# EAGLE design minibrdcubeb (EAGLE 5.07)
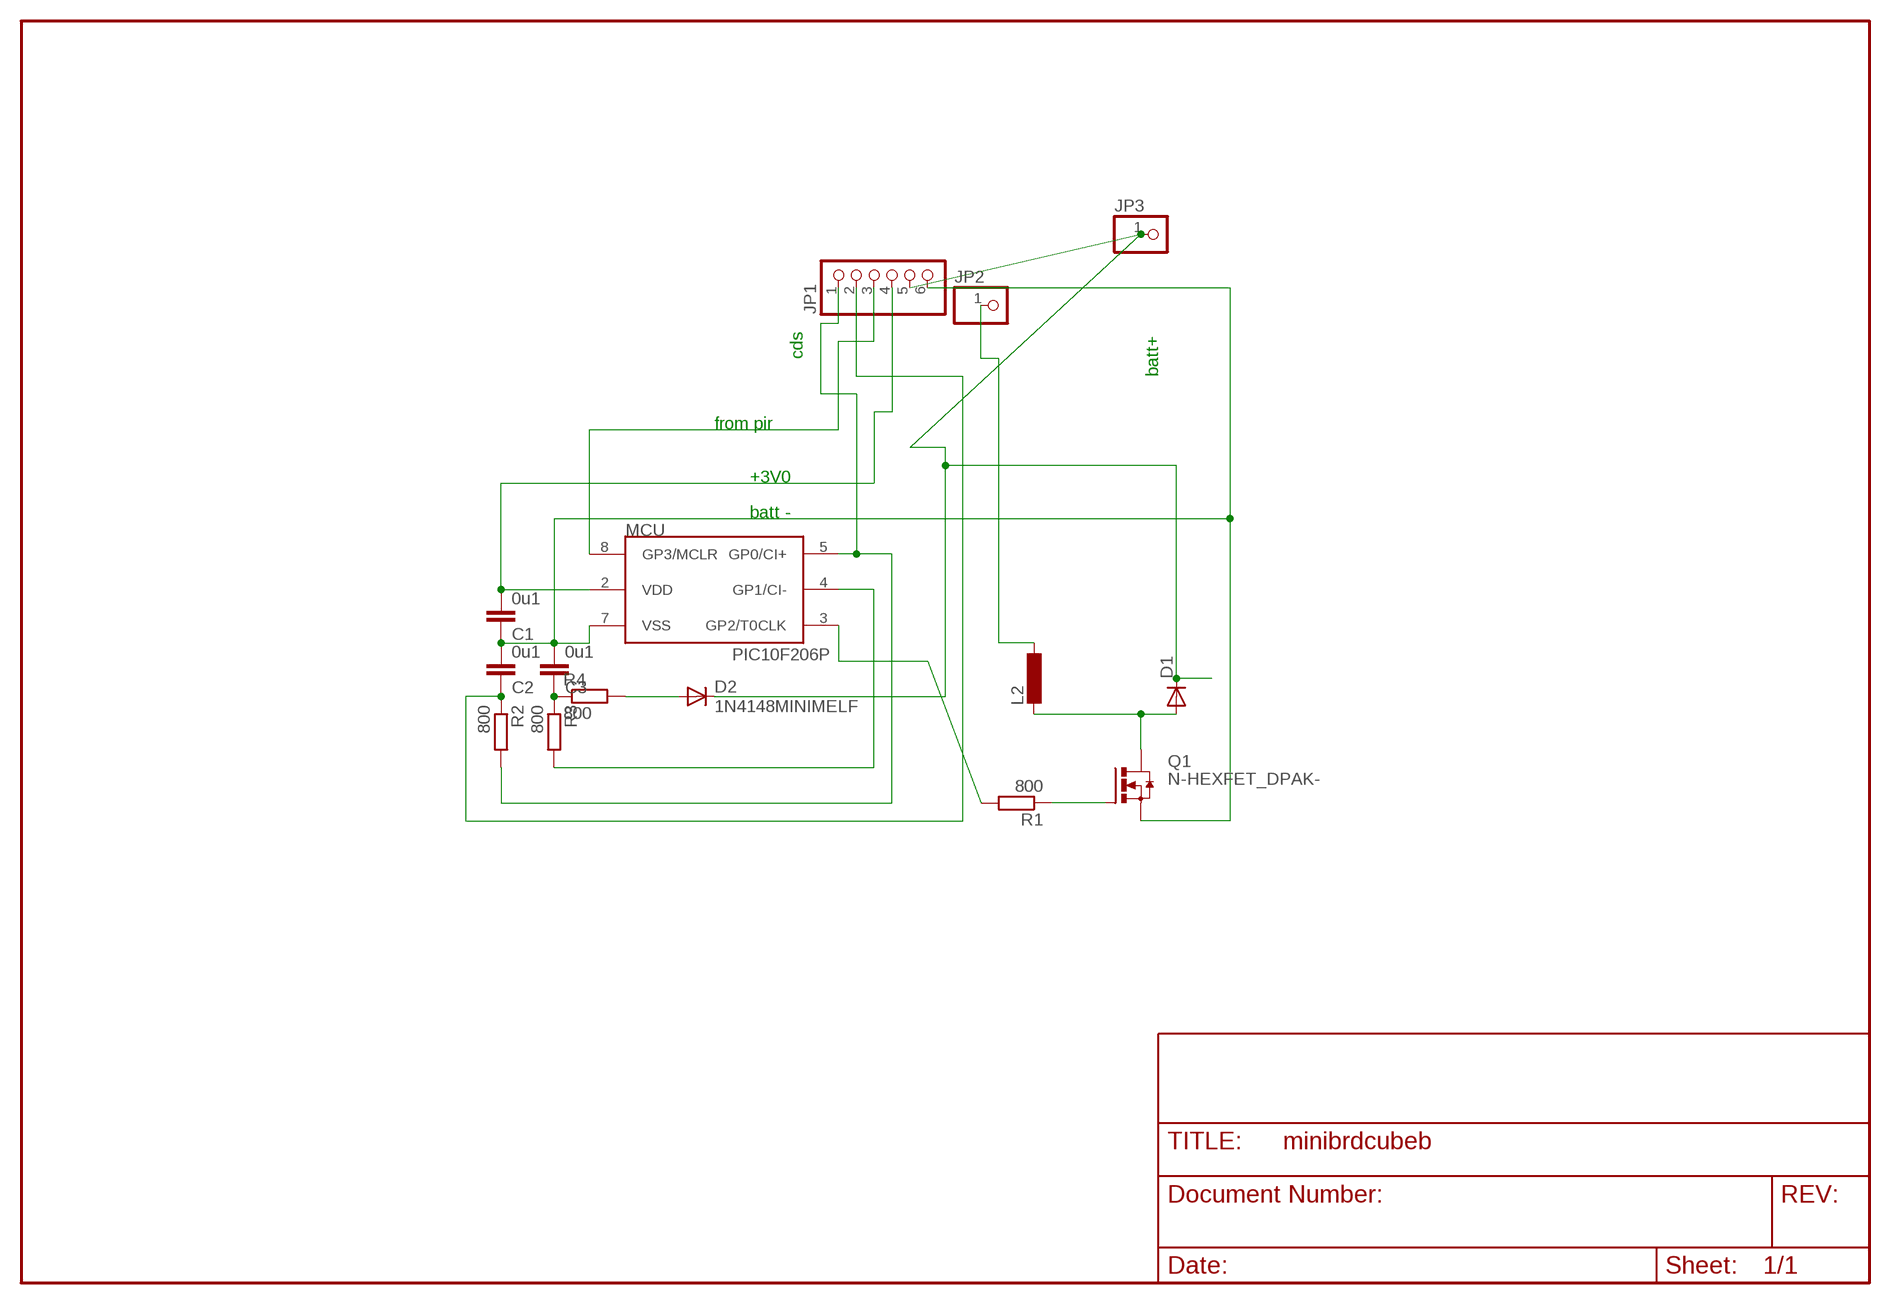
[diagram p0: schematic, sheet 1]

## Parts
C1  0u1  C-EUC1206  [C1206]
C2  0u1  C-EUC1206  [C1206]
C3  0u1  C-EUC1206  [C1206]
D1  DIODE-SMC  [SMC]
D2  1N4148MINIMELF  [MINIMELF]
JP1  PINHD-1X6  [1X06BOX]
JP2  PINHD-1X11X0.4  [1X01]
JP3  PINHD-1X11X0.4  [1X01]
L2  L-EUPIS2816  [PIS2816]
MCU  PIC10F206P  [DIL8]
Q1  N-HEXFET_DPAK-  [TO252]
R1  800  R-EU_R0805  [R0805]
R2  800  R-EU_R1206  [R1206]
R3  800  R-EU_R1206  [R1206]
R4  800  R-EU_R1206  [R1206]

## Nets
N$1: D2.A R4.2
N$2: JP1.1 MCU.5(GP0/CI+) R2.2
N$3: D1.C D2.C JP1.5 JP3.1
N$4: MCU.4(GP1/CI-) R3.2
N$5: D1.A L2.2 Q1.3(D)
N$6: C1.2 JP1.4 MCU.2(VDD)
N$7: Q1.1(G) R1.1
N$8: JP2.1 L2.1
N$10: C3.1 R3.1 R4.1
N$11: C2.1 JP1.2 R2.1
N$13: JP1.3 MCU.8(GP3/MCLR)
N$14: MCU.3(GP2/T0CLK) R1.2
VSS: C1.1 C2.2 C3.2 JP1.6 MCU.7(VSS) Q1.2(S)

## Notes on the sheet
- cds
- batt+
- from pir
- +3V0
- batt -

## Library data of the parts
C1-C3 = rcl:C-EU: CAPACITOR, European symbol
D1 = diode-1:DIODE-: DIODE
D2 = diode-1:1N4148: DIODE
JP1 = pinhead:PINHD-1X6: PIN HEADER
JP2 JP3 = pinhead:PINHD-1X1: PIN HEADER
L2 = rcl:L-EU: INDUCTOR, European symbol
MCU = microchip-3:PIC10F2*: uPC nW 0,25/0,5k Program Flash memory Comparator
Q1 = transistor-power:N-HEXFET_?-*: HEXFET® Power MOSFET
R1-R4 = rcl:R-EU_: RESISTOR, European symbol

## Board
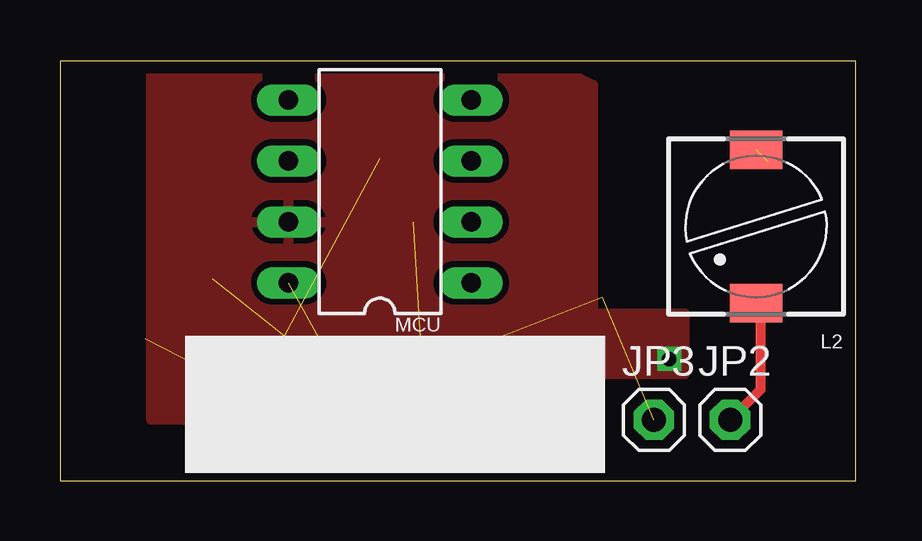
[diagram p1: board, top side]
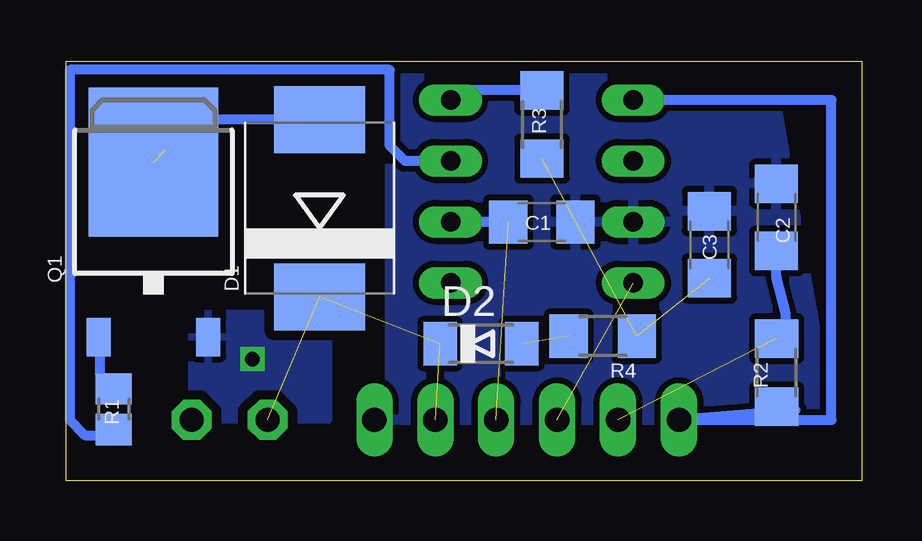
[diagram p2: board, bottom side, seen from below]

Size 33.17 x 17.5 mm. Coordinates in mm from the lower left corner, seen from the top.
Outline: 0,0 33.17,0 33.17,17.5 0,17.5 0,0
Copper layers (1*16): Top 0.035mm / dielectric 1.5mm / Bottom 0.035mm
Design rules "default *": minimum track width 10mil, minimum drill 24mil, track to track 8mil, track to pad 8mil, pad to pad 8mil, via to via 8mil, smd to smd 8mil, copper to edge 20mil, drill to drill 8mil, minimum pad ring 10mil, minimum via ring 8mil, stop-mask expansion 4mil, vias tented up to drill 0mil, thermal gap 10mil

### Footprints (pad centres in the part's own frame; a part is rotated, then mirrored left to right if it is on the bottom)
C1206 = smd 1.6 x 1.8: 1 -1.4,0; 2 1.4,0
SMC = smd 2.8 x 3.8: A 3.7,0; C -3.7,0
MINIMELF = smd 1.4 x 1.8: A 1.7,0; C -1.7,0
1X06BOX = drill 1.016 long: 1 -6.35,0; 2 -3.81,0; 3 -1.27,0; 4 1.27,0; 5 3.81,0; 6 6.35,0
1X01 = drill 1 pad 1.676 octagon: 1 0,0
PIS2816 = smd 2.2 x 1.6: 1 0,3.2; 2 0,-3.2
DIL8 = drill 0.813 long: 1 -3.81,-3.81; 2 -1.27,-3.81; 3 1.27,-3.81; 4 3.81,-3.81; 5 3.81,3.81; 6 1.27,3.81; 7 -1.27,3.81; 8 -3.81,3.81
TO252 = smd 1 x 1.6: 1 -2.28,-3.53; 2 2.28,-3.53 | smd 5.4 x 6.2: 3 0,3.77
R0805 = smd 1.3 x 1.5: 1 -0.85,0; 2 0.85,0
R1206 = smd 1.6 x 1.803: 1 -1.422,0; 2 1.422,0

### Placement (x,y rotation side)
C1  13.34,10.79 180 bottom
C2  3.56,10.99 90 bottom
C3  6.35,9.84 90 bottom
D1  22.61,11.37 90 bottom
D2  15.88,5.71 0 bottom
JP1  13.97,2.54 0 top
JP2  27.94,2.54 0 top
JP3  24.77,2.54 0 top
L2  29.02,10.6 180 top
MCU  13.34,12.06 90 top
Q1  29.53,9.53 0 bottom
R1  31.18,2.98 270 bottom
R2  3.56,4.51 270 bottom
R3  13.34,14.86 90 bottom
R4  10.79,6.03 180 bottom

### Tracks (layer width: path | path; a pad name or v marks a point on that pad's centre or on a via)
N$1  (1 unrouted)
N$2
  Bottom 0.406: MCU.5 1.27,15.88 1.27,2.54 JP1.1 2.77,2.95 R2.2
N$3  (3 unrouted)
N$4
  Bottom 0.406: R3.2 16.74,16.28 MCU.4
N$5  (1 unrouted)
  Bottom 0.406: D1.A 27.76,15.07 Q1.3
N$6  (1 unrouted)
  Bottom 0.406: C1.2 MCU.2
N$7
  Bottom 0.406: R1.1 31.18,3.87 31.75,4.45 31.75,5.94 Q1.1
N$8
  Top 0.406: JP2.1 29.21,3.81 29.21,7.21 L2.1
N$10  (2 unrouted)
N$11  (1 unrouted)
  Bottom 0.406: C2.1 3.56,8.51 3.17,6.99 3.17,6.07 R2.1
N$13  (1 unrouted)
N$14
  Bottom 0.406: MCU.3 19.05,13.34 19.69,13.97 19.69,17.14 33.02,17.14 33.02,2.54 32.38,1.91 31.41,1.91 R1.2
VSS  (via drill 0.6)
  other vias: 25.4,5.08
  pour Bottom (isolate 0.254): 3.81,17.14 19.69,17.14 19.69,2.54 1.27,2.54
  pour Top (isolate 0.254): 3.81,17.14 20.96,17.14 22.23,16.51 22.23,6.99 26.04,6.99 26.04,4.45 21.59,4.45 21.59,2.54 3.81,2.54
  pour Bottom (isolate 0.406): 22.23,6.99 27.94,6.99 27.94,3.81 26.67,2.54 22.23,2.54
